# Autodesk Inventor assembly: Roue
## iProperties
Created: 2002-04
Part Number: Roue
Document SubType Name: Assemblage
Designer: Flavien MARTY
Control State: 0
Master: False
Checked Out: False
Shininess: 41.0
Length Units: 11269
Angle Units: 11279
Time Units: 11290
Mass Units: 11283
Length Display Precision: 3
Angle Display Precision: 2
Compacted: True
Density: 0.0
Volumn: 0.0
Area: 0.0
PropertySet Name: Model Information
Author: Flavien MARTY
